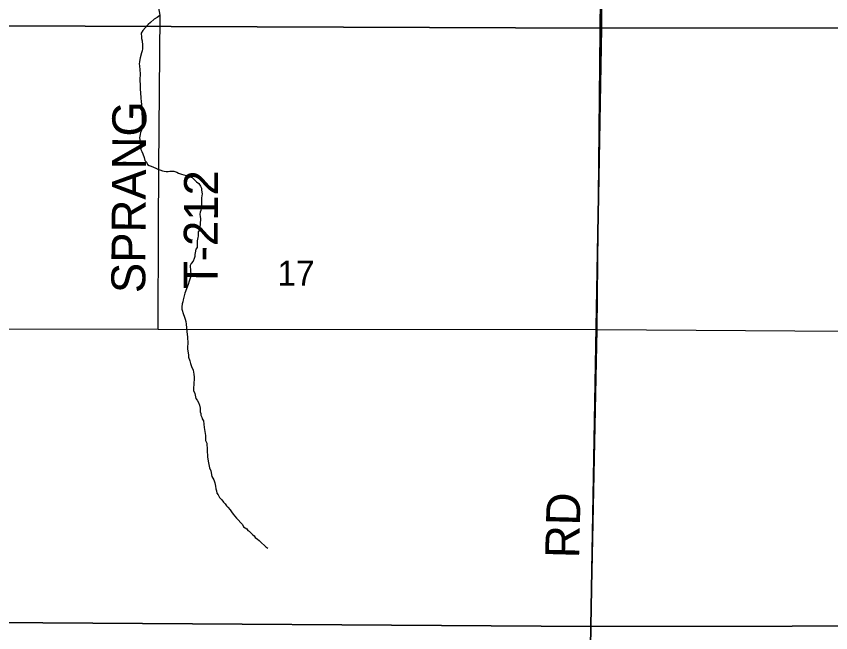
# Model space of a CAD drawing. Extents: x 0 to 34, y 0 to 22.
# Drawn here: x 3.538 to 4.9, y 17.445 to 18.476 of the extents above; entities that cross this region are included whole.
import ezdxf

# ---------------------------------------------------------------- set-up
doc = ezdxf.new("R2010")
doc.units = 0
for name, color, linetype in [('GM_X_County_Road', 7, 'Continuous'), ('GM_X_Minor_River', 7, 'Continuous'), ('GM_X_Section', 7, 'Continuous'), ('GM_X_Section_Text', 7, 'Continuous'), ('GM_X_Township_Road', 7, 'Continuous'), ('GM_X_Township_Road_Text', 7, 'Continuous')]:
    doc.layers.add(name, color=color, linetype=linetype)

msp = doc.modelspace()

# ---------------------------------------------------------------- linework, layer by layer
at = {"layer": 'GM_X_County_Road'}
for points in [[(3.4203, 17.953), (3.775, 17.9527), (4.5096, 17.9519)], [(4.5096, 17.9519), (5.0061, 17.9488), (5.4754, 17.9533), (5.7574, 17.9498)]]:
    msp.add_lwpolyline(points, dxfattribs=at)
at = {"layer": 'GM_X_Minor_River'}
for points in [[(3.7781, 18.477), (3.7735, 18.4737), (3.7682, 18.4708), (3.7624, 18.4652), (3.7585, 18.4618), (3.7496, 18.4518), (3.7468, 18.4473), (3.7471, 18.4408), (3.7474, 18.4382), (3.7481, 18.4344), (3.7487, 18.4275), (3.7486, 18.4211), (3.7481, 18.4177), (3.7473, 18.4143), (3.7452, 18.406), (3.7444, 18.4033), (3.7436, 18.3996), (3.7435, 18.3962), (3.7438, 18.3927), (3.7441, 18.3859), (3.7447, 18.3791), (3.7445, 18.3696), (3.745, 18.3597), (3.7449, 18.3525), (3.7455, 18.3487), (3.7461, 18.3384), (3.7464, 18.3335), (3.747, 18.3278), (3.7476, 18.3221), (3.7479, 18.3168), (3.7478, 18.3122), (3.7485, 18.3077), (3.7482, 18.2952), (3.7473, 18.2872), (3.7469, 18.2846), (3.7457, 18.2812), (3.7448, 18.2778), (3.744, 18.2725), (3.7443, 18.2694), (3.7442, 18.2657), (3.7449, 18.263), (3.7452, 18.2596), (3.7459, 18.2561), (3.7462, 18.2531), (3.7476, 18.2493), (3.7494, 18.2454), (3.7516, 18.2393), (3.753, 18.2344), (3.7556, 18.2317), (3.7574, 18.2278), (3.76, 18.2263), (3.7634, 18.2251), (3.7709, 18.2215), (3.7754, 18.2195), (3.778, 18.2187), (3.7822, 18.2171), (3.7852, 18.2167), (3.7886, 18.2162), (3.7916, 18.2162), (3.7947, 18.2165), (3.8011, 18.2164), (3.8063, 18.2147), (3.8093, 18.2132), (3.8139, 18.2119), (3.818, 18.2107), (3.8218, 18.2095), (3.8319, 18.2059), (3.8356, 18.2024), (3.8393, 18.1989), (3.8431, 18.1958), (3.846, 18.1916), (3.8474, 18.1885), (3.8478, 18.1855), (3.8481, 18.1813), (3.8484, 18.1786), (3.8475, 18.1718), (3.8474, 18.1692), (3.8477, 18.1638), (3.8476, 18.1608), (3.8472, 18.1574), (3.8471, 18.1544), (3.8463, 18.151), (3.8455, 18.1479), (3.845, 18.1445), (3.8453, 18.1404), (3.8456, 18.1373)], [(3.8456, 18.1373), (3.8454, 18.1278), (3.8441, 18.118), (3.8421, 18.115), (3.8417, 18.1116), (3.842, 18.1082), (3.8412, 18.1056), (3.8403, 18.0999), (3.8401, 18.0889), (3.8381, 18.0863), (3.8369, 18.0802), (3.8364, 18.0772), (3.8364, 18.0742), (3.8355, 18.0708), (3.8335, 18.0663), (3.8304, 18.0621), (3.8288, 18.0591), (3.8288, 18.0561), (3.8291, 18.0527), (3.8294, 18.05), (3.8297, 18.044), (3.8296, 18.0405), (3.8288, 18.0379), (3.8268, 18.033), (3.8251, 18.027), (3.8227, 18.0202), (3.8199, 18.0127), (3.817, 18.0017), (3.8162, 17.9983), (3.8154, 17.9946), (3.8145, 17.99), (3.8148, 17.9862), (3.8177, 17.9771), (3.8187, 17.974), (3.8202, 17.969), (3.8212, 17.9652), (3.8219, 17.9607), (3.8225, 17.955), (3.8231, 17.9485), (3.8234, 17.9436), (3.8241, 17.9398), (3.8244, 17.9356), (3.8247, 17.9322), (3.8244, 17.9193), (3.8257, 17.9094), (3.826, 17.9056), (3.8282, 17.8998), (3.8292, 17.8953), (3.831, 17.8899), (3.8335, 17.8838), (3.8345, 17.8773), (3.8352, 17.872), (3.8351, 17.8675), (3.8346, 17.8637), (3.8345, 17.8606), (3.834, 17.8538), (3.8343, 17.85), (3.8365, 17.8447), (3.8382, 17.8367), (3.8404, 17.834), (3.8426, 17.8301), (3.844, 17.8256), (3.8451, 17.8206), (3.8453, 17.8142), (3.8464, 17.8115), (3.8467, 17.8088), (3.8482, 17.8054), (3.8489, 17.8027), (3.8507, 17.7993), (3.852, 17.7882), (3.854, 17.7749), (3.8545, 17.7666), (3.8563, 17.762), (3.8569, 17.751), (3.8577, 17.7384), (3.8591, 17.7293), (3.8612, 17.7209), (3.8629, 17.7156), (3.865, 17.706), (3.8683, 17.7007), (3.8697, 17.6957), (3.8711, 17.69), (3.8718, 17.6854), (3.8725, 17.6824), (3.8731, 17.6782), (3.8754, 17.6755), (3.8779, 17.6713), (3.8816, 17.667), (3.8846, 17.6635), (3.8872, 17.6605), (3.8894, 17.6574), (3.8916, 17.6547), (3.8957, 17.6504), (3.8975, 17.6474), (3.9008, 17.6431), (3.9063, 17.6366), (3.9163, 17.6261), (3.9178, 17.6223), (3.9204, 17.6203), (3.9234, 17.6188), (3.9248, 17.6161)], [(3.9248, 17.6161), (3.9275, 17.6149), (3.933, 17.6091), (3.9356, 17.6071), (3.9371, 17.6041), (3.9412, 17.6013), (3.9438, 17.599), (3.9479, 17.5955), (3.9527, 17.5909), (3.9553, 17.5885), (3.9587, 17.5862)]]:
    msp.add_lwpolyline(points, dxfattribs=at)
at = {"layer": 'GM_X_Section'}
for points in [[(4.5252, 19.4639), (4.517, 18.4555), (3.5082, 18.4594), (3.5253, 19.4614)], [(5.5276, 19.4562), (5.5161, 18.4568), (4.517, 18.4555), (4.5252, 19.4639)], [(4.517, 18.4555), (4.4991, 17.4554), (3.4982, 17.462), (3.5082, 18.4594)], [(5.5161, 18.4568), (5.5087, 17.4571), (4.4991, 17.4554), (4.517, 18.4555)], [(4.4991, 17.4554), (4.4826, 16.453), (3.4692, 16.4646), (3.4982, 17.462)], [(5.5087, 17.4571), (5.4956, 16.4418), (4.4826, 16.453), (4.4991, 17.4554)]]:
    msp.add_lwpolyline(points, close=True, dxfattribs=at)
at = {"layer": 'GM_X_Township_Road'}
for p, q in [((4.5096, 17.9519), (4.5176, 18.7828)), ((4.486, 16.8389), (4.5096, 17.9519))]:
    msp.add_line(p, q, dxfattribs=at)
for points in [[(3.7763, 18.2226), (3.7785, 18.4772), (3.7705, 18.5198), (3.7706, 18.8127), (3.7739, 18.8252), (3.7671, 18.8549), (3.7401, 18.9237), (3.7195, 19.0346)], [(3.775, 17.9527), (3.7754, 18.1232), (3.7763, 18.2206), (3.7763, 18.2226)]]:
    msp.add_lwpolyline(points, dxfattribs=at)

# ---------------------------------------------------------------- texts
at = {"layer": 'GM_X_Section_Text'}
msp.add_text('17', height=0.04186, rotation=0, dxfattribs=at).set_placement((3.9745, 18.0252))
at = {"layer": 'GM_X_Township_Road_Text'}
for s, rotation, p in [('SPRANG', 89.6516, (3.7534, 18.0126)), ('T-212', 89.7193, (3.8743, 18.0196)), ('RD', 88.5175, (4.4792, 17.569))]:
    msp.add_text(s, height=0.05682, rotation=rotation, dxfattribs=at).set_placement(p)

doc.saveas('drawing.dxf')
